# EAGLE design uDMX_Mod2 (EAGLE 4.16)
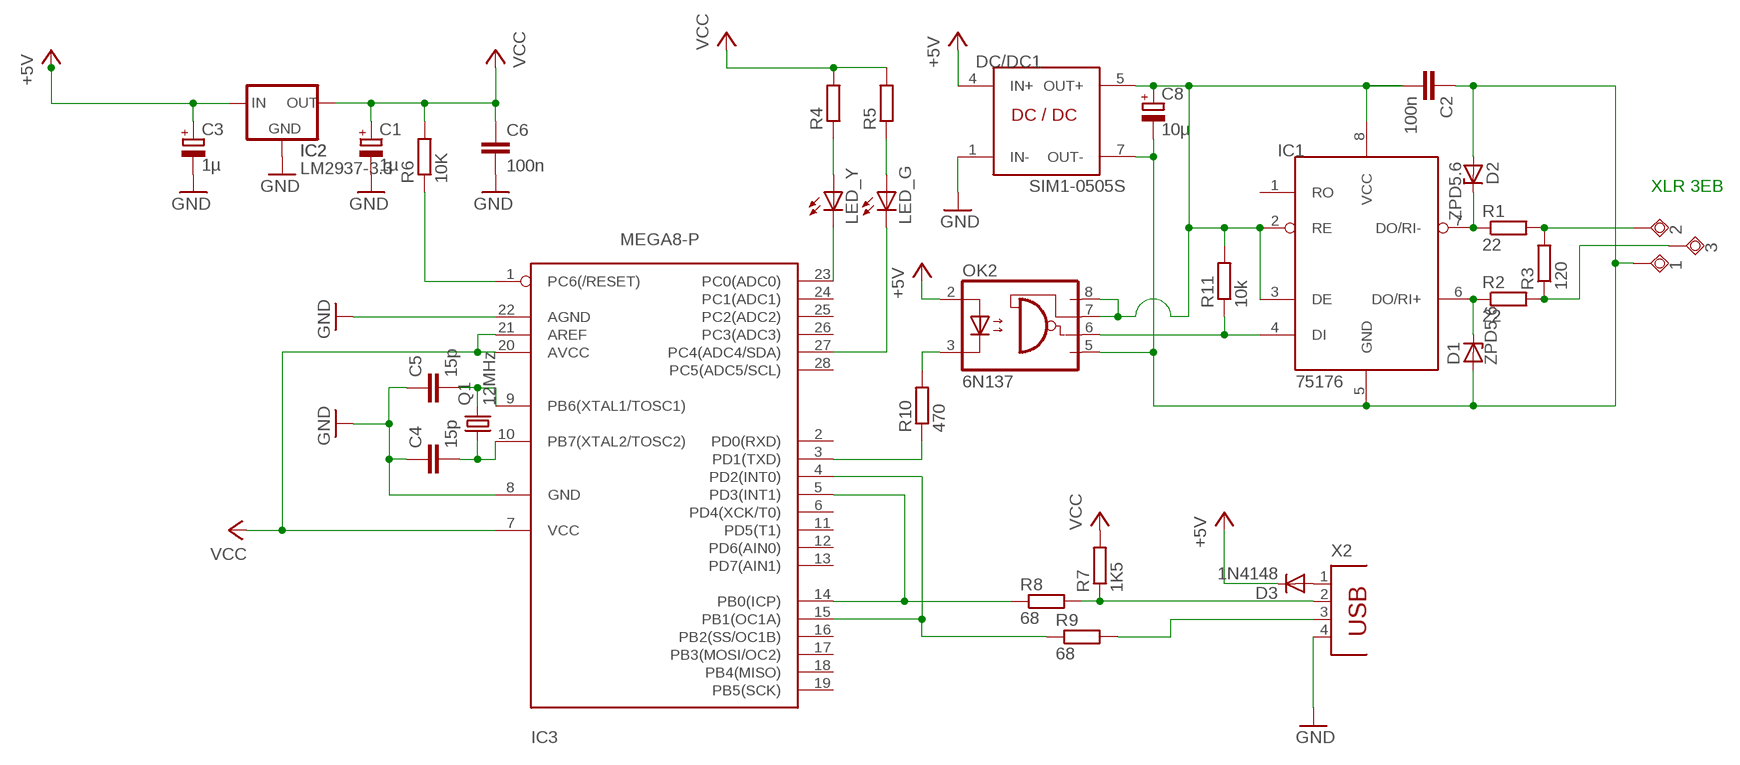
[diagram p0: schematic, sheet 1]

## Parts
1  PAD  [PAD]
2  PAD  [PAD]
3  PAD  [PAD]
C1  1µ  CPOL-EUE2.5-5  [E2,5-5]
C2  100n  C2.5/4  [C2.5-4]
C3  1µ  CPOL-EUE2.5-5  [E2,5-5]
C4  15p  C2.5/4  [C2.5-4]
C5  15p  C2.5/4  [C2.5-4]
C6  100n  C2.5/4  [C2.5-4]
C8  10µ  CPOL-EUE2.5-5  [E2,5-5]
D1  ZPD5.6  ZPD  [DO35Z10]
D2  ZPD5.6  ZPD  [DO35Z10]
D3  1N4148  [DO35-10]
DC/DC1  SIM1-0505S  [DIL08]
IC1  75176  [DIL08]
IC2  LM2937-3.3  LM2937  [TO220S]
IC3  MEGA8-P  [DIL28-3]
LED_G  LED3MM  [LED3MM]
LED_Y  LED3MM  [LED3MM]
OK2  6N137  [DIL08]
Q1  12MHz  CRYSTALHC18U-V  [HC18U-V]
R1  22  R-EU_0207/10  [0207/10]
R2  22  R-EU_0207/10  [0207/10]
R3  120  R-EU_0207/10  [0207/10]
R4  R-EU_0207/10  [0207/10]
R5  R-EU_0207/10  [0207/10]
R6  10K  R-EU_0207/10  [0207/10]
R7  1K5  R-EU_0207/10  [0207/10]
R8  68  R-EU_0207/10  [0207/10]
R9  68  R-EU_0207/10  [0207/10]
R10  470  R-EU_0207/10  [0207/10]
R11  10k  R-EU_0207/10  [0207/10]
X2  PN61729  [PN61729]

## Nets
+5V: C3.+ D3.C DC/DC1.4(IN+) IC2.1(IN) OK2.2(A)
D-: R7.1 R8.2 X2.2
DMX2: 2.P$1(TP) R1.2 R3.2
GND: C1.- C3.- C4.1 C5.1 C6.2 DC/DC1.1(IN-) IC2.2(GND) IC3.8(GND) IC3.22(AGND) X2.4
N$1: IC3.5(PD3(INT1)) IC3.14(PB0(ICP)) R8.1
N$2: OK2.3(C) R10.2
N$3: D2.C IC1.7(DO/RI-) R1.1
N$4: D1.C IC1.6(DO/RI+) R2.1
N$5: IC3.3(PD1(TXD)) R10.1
N$6: IC3.4(PD2(INT0)) IC3.15(PB1(OC1A)) R9.1
N$7: LED_Y.A R4.1
N$8: LED_G.A R5.1
N$9: IC3.23(PC0(ADC0)) LED_Y.K(C)
N$10: R9.2 X2.3
N$11: IC3.27(PC4(ADC4/SDA)) LED_G.K(C)
N$13: 3.P$1(TP) R2.2 R3.1
N$14: D3.A X2.1
N$16: C2.2 C8.+ DC/DC1.5(OUT+) IC1.2(RE) IC1.3(DE) IC1.8(VCC) OK2.7(VE) OK2.8(VCC) R11.2
N$17: 1.P$1(TP) C2.1 C8.- D1.A D2.A DC/DC1.7(OUT-) IC1.5(GND) OK2.5(GND)
N$20: IC1.4(DI) OK2.6(VO) R11.1
N$37: C4.2 IC3.10(PB7(XTAL2/TOSC2)) Q1.1
N$38: C5.2 IC3.9(PB6(XTAL1/TOSC1)) Q1.2
N$47: IC3.1(PC6(/RESET)) R6.1
VCC: C1.+ C6.1 IC2.3(OUT) IC3.7(VCC) IC3.20(AVCC) IC3.21(AREF) R4.2 R5.2 R6.2 R7.2
Unconnected: IC1.1(RO) IC3.2(PD0(RXD)) IC3.6(PD4(XCK/T0)) IC3.11(PD5(T1)) IC3.12(PD6(AIN0)) IC3.13(PD7(AIN1)) IC3.16(PB2(SS/OC1B)) IC3.17(PB3(MOSI/OC2)) IC3.18(PB4(MISO)) IC3.19(PB5(SCK)) IC3.24(PC1(ADC1)) IC3.25(PC2(ADC2)) IC3.26(PC3(ADC3)) IC3.28(PC5(ADC5/SCL))

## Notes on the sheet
- XLR 3EB

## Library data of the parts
1-3 = div:PAD
C1 C3 C8 = rcl:CPOL-EU: POLARIZED CAPACITOR, European symbol
C2 C4-C6 = capacitor-wima:C: CAPACITOR
D1 D2 = diode:ZPD: Z DIODE
D3 = diode:1N4148: DIODE
DC/DC1 = Lutz:SIM1-0505S
IC1 = Lutz:75176
IC2 = Lutz:LM2937: VOLTAGE REGULATOR
IC3 = atmel:MEGA8-P: MICROCONTROLLER 8 Kbytes FLASH 1 kbytes SRAM 512 bytes EEPROM USART 4-channel 10 bit ADC 2-channel 8 bit ADC Source: avr.lbr
LED_G LED_Y = led:LED: LED
OK2 = optocoupler:6N137: MOTOROLA OPTO COUPLER
Q1 = crystal:CRYSTAL: CRYSTAL
R1-R11 = rcl:R-EU_: RESISTOR, European symbol
X2 = con-berg:PN61729: BERG USB connector

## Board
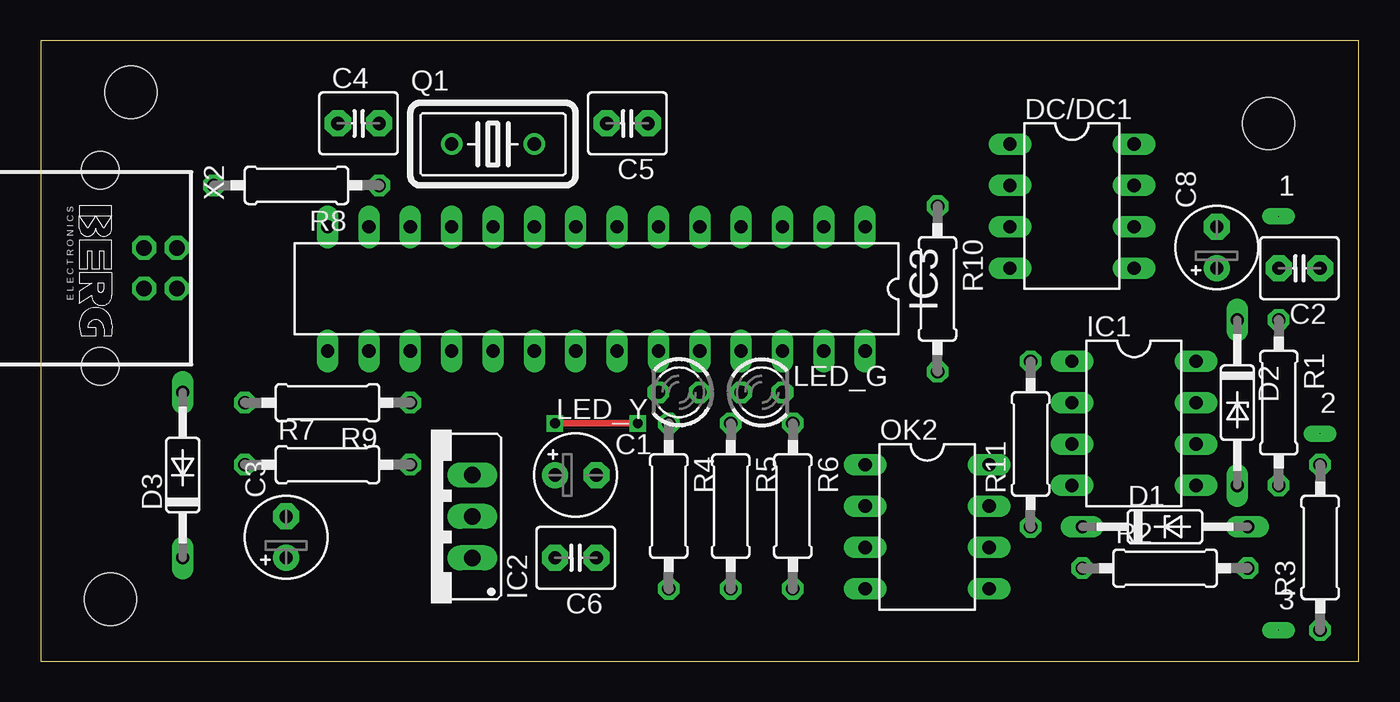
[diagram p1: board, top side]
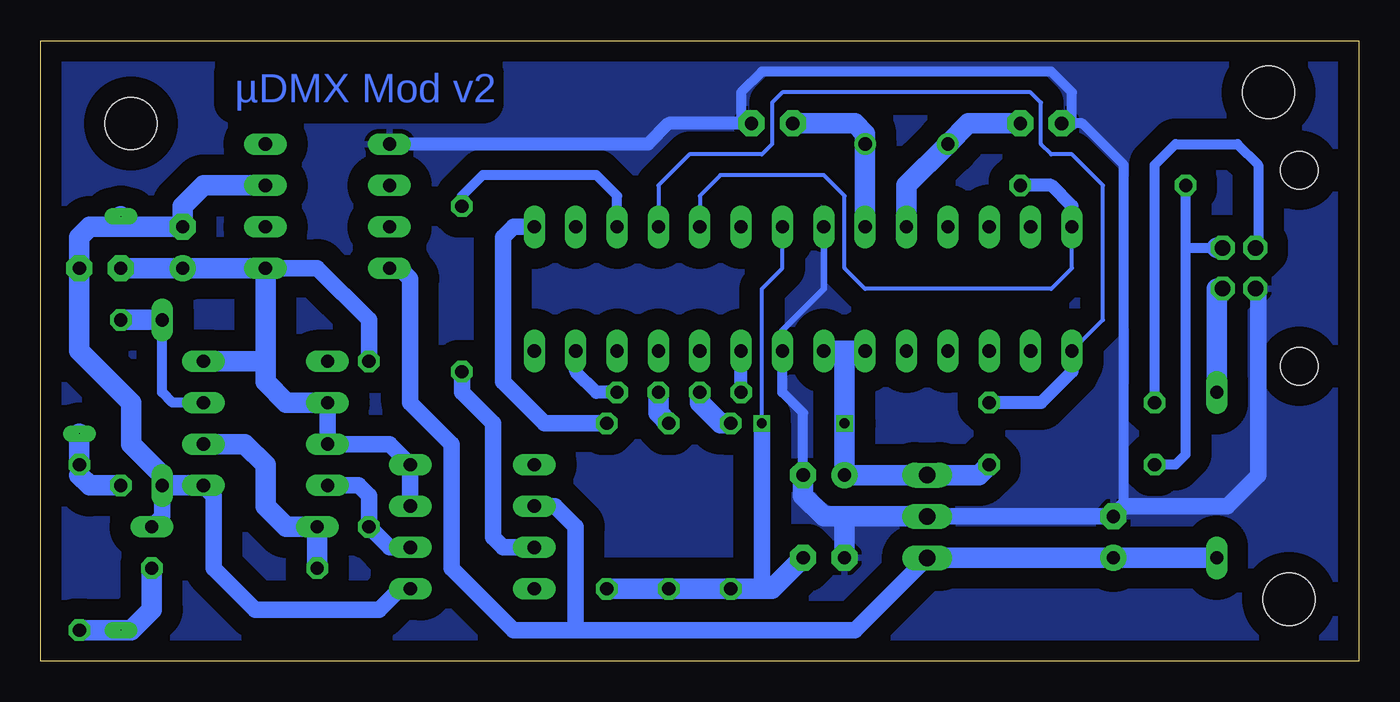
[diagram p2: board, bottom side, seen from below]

Size 80.95 x 38.09 mm. Coordinates in mm from the lower left corner, seen from the top.
Outline: 0,0 80.95,0 80.95,38.09 0,38.09 0,0
Copper layers (1*16): Top 0.035mm / dielectric 1.5mm / Bottom 0.035mm
Design rules "default": minimum track width 10mil, minimum drill 24mil, track to track 8mil, track to pad 8mil, pad to pad 8mil, via to via 8mil, smd to smd 8mil, copper to edge 40mil, drill to drill 8mil, minimum pad ring 10mil, minimum via ring 8mil, stop-mask expansion 4mil, vias tented up to drill 0mil, thermal gap 10mil
Holes 3.2 mm at 5.55,34.92 75.4,33.02 4.28,3.8

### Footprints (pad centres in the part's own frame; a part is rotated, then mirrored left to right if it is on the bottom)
PAD = drill 0.031 pad 1.016 long: P$1 0,0
E2,5-5 = drill 0.813 pad 1.6 round: + -1.27,0 | drill 0.813 pad 1.6 octagon: - 1.27,0
C2.5-4 = drill 0.813 pad 1.6 octagon: 1 -1.27,0; 2 1.27,0
DO35Z10 = drill 0.813 long: A 5.08,0; C -5.08,0
DO35-10 = drill 0.813 long: A 5.08,0; C -5.08,0
DIL08 = drill 0.813 long: 1 -3.81,-3.81; 2 -1.27,-3.81; 3 1.27,-3.81; 4 3.81,-3.81; 5 3.81,3.81; 6 1.27,3.81; 7 -1.27,3.81; 8 -3.81,3.81
TO220S = drill 1.016 long: 1 -2.54,-2.54; 2 0,-2.54; 3 2.54,-2.54
DIL28-3 = drill 0.813 long: 1 -16.51,-3.81; 2 -13.97,-3.81; 3 -11.43,-3.81; 4 -8.89,-3.81; 5 -6.35,-3.81; 6 -3.81,-3.81; 7 -1.27,-3.81; 8 1.27,-3.81; 9 3.81,-3.81; 10 6.35,-3.81; 11 8.89,-3.81; 12 11.43,-3.81; 13 13.97,-3.81; 14 16.51,-3.81; 15 16.51,3.81; 16 13.97,3.81; 17 11.43,3.81; 18 8.89,3.81; 19 6.35,3.81; 20 3.81,3.81; 21 1.27,3.81; 22 -1.27,3.81; 23 -3.81,3.81; 24 -6.35,3.81; 25 -8.89,3.81; 26 -11.43,3.81; 27 -13.97,3.81; 28 -16.51,3.81
LED3MM = drill 0.813 octagon: A -1.27,0; K 1.27,0
HC18U-V = drill 0.813 round: 1 -2.54,0; 2 2.54,0
0207/10 = drill 0.813 octagon: 1 -5.08,0; 2 5.08,0
PN61729 = drill 0.95 octagon: 1 1.25,4.71; 2 -1.25,4.71; 3 -1.25,2.71; 4 1.25,2.71 | hole 2.3: -6.02,0; 6.02,0

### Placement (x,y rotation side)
1  76.04,27.3 0 top
2  78.58,13.96 0 top
3  76.04,1.9 0 top
C1  32.85,11.43 0 top
C2  77.31,24.12 180 top
C3  15.08,7.61 90 top
C4  19.52,33.02 0 top
C5  36.03,33.02 180 top
C6  32.85,6.34 180 top
C8  72.23,25.39 90 top
D1  69.05,8.25 0 top
D2  73.5,15.87 270 top
D3  8.72,11.43 90 top
DC/DC1  63.33,27.94 270 top
IC1  67.15,14.6 270 top
IC2  23.96,8.88 90 top
IC3  34.12,22.85 180 top
LED_G  44.28,16.51 0 top
LED_Y  39.2,16.51 180 top
OK2  54.45,8.25 270 top
Q1  27.78,31.74 0 top
R1  76.04,15.87 270 top
R2  69.05,5.71 0 top
R3  78.58,6.98 90 top
R4  38.57,9.52 270 top
R5  42.38,9.52 270 top
R6  46.19,9.52 270 top
R7  17.62,12.06 0 top
R8  15.71,29.2 180 top
R9  17.62,15.87 180 top
R10  55.08,22.85 270 top
R11  60.79,13.33 90 top
X2  3.65,24.12 270 top

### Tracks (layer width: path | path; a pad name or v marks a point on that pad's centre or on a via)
+5V
  Bottom 1.016: IC2.1 30.95,1.9 48.09,1.9 | 48.09,1.9 51.9,1.9 55.71,5.71 55.71,13.33 58.25,15.87 58.25,23.49 58.89,24.12 DC/DC1.4 | OK2.2 49.36,9.52 48.09,8.25 48.09,1.9
  Bottom 1.27: D3.C C3.+ IC2.1
D-
  Bottom 0.61: R7.1 11.27,12.06 10.63,12.7 10.63,25.39 | 10.63,25.39 8.72,25.39 | 10.63,25.39 R8.2
  Bottom 1.27: 8.72,25.39 X2.2
DMX2
  Bottom 0.406: 78.58,11.43 R3.2
  Bottom 1.27: R1.2 77.94,10.79 78.58,11.43 | R3.2 2.P$1
GND
  Bottom 0.406: IC3.8 32.85,22.85 35.39,20.31 IC3.22
  Bottom 0.61: 37.93,33.02 37.93,34.92 36.66,36.19 18.89,36.19 17.62,34.92 17.62,33.02 16.98,33.02 14.44,30.48 14.44,9.52 | IC3.22 35.39,16.51 34.12,15.23 C1.-
  Bottom 0.813: DC/DC1.1 43.65,31.74 42.38,33.02 37.93,33.02 C5.1 | 17.62,33.02 C4.1
  Bottom 1.016: X2.4 6.19,22.88 6.19,11.43 8.09,9.52 14.44,9.52 C3.- IC2.2
  Bottom 1.27: IC2.2 31.59,8.88 | 31.59,8.88 32.85,8.88 34.12,10.16 C1.- | 31.59,8.88 C6.2
  pour Bottom (isolate 1.27): -0.8,38.73 81.75,38.73 81.75,-0.64 -0.8,-0.64
N$1
  Bottom 0.254: IC3.14 17.62,24.12 18.89,22.85 30.32,22.85 31.59,24.12 31.59,28.57 32.85,29.84 39.2,29.84 40.47,28.57 IC3.5
  Bottom 0.813: IC3.14 17.62,27.94 18.89,29.2 R8.1
N$2
  Bottom 1.016: OK2.3 52.54,6.98 53.17,7.61 53.17,14.6 55.08,16.51 R10.2
N$3
  Bottom 0.61: IC1.7 72.86,15.87 73.5,16.51 D2.C
  Bottom 1.27: D2.C R1.1
N$4
  Bottom 1.27: IC1.6 68.42,13.33 67.15,12.06 67.15,9.52 65.88,8.25 D1.C R2.1
N$5
  Bottom 0.61: R10.1 55.08,28.57 53.81,29.84 46.82,29.84 45.55,28.57 IC3.3
N$6
  Bottom 0.254: IC3.4 43.01,29.2 41.11,31.11 36.66,31.11 36.03,31.74 36.03,34.28 35.39,34.92 20.16,34.92 19.52,34.28 19.52,31.74 18.89,31.11 17.62,31.11 15.71,29.2 15.71,20.95 IC3.15
  Bottom 0.813: R9.1 19.52,15.87 17.62,17.77 IC3.15
N$7
  Bottom 1.27: R4.1 39.2,14.6 40.47,15.87 LED_Y.A
N$8
  Bottom 1.27: R5.1 43.01,15.23 LED_G.A
N$9
  Bottom 0.813: LED_Y.K IC3.23
N$10
  Bottom 0.406: 6.19,25.39 6.21,25.38 X2.3
  Bottom 0.61: R9.2 12.54,30.48 11.27,31.74 7.46,31.74 6.19,30.48 6.19,25.39
N$11
  Bottom 0.813: LED_G.K 46.82,16.51 48.09,17.77 IC3.27
N$13
  Bottom 1.27: R2.2 74.13,3.17 75.4,1.9 3.P$1 R3.1
N$14
  Bottom 1.27: D3.A 8.72,22.85 X2.1
N$16
  Bottom 1.016: IC1.2 IC1.3 59.52,13.33 OK2.8 OK2.7 | R11.2 60.79,20.95 63.97,24.12 DC/DC1.5
  Bottom 1.27: IC1.2 65.88,15.87 67.15,17.14 67.15,18.41 | 67.15,18.41 IC1.8 | 67.15,18.41 DC/DC1.5 C8.+ C2.2
N$17
  Bottom 1.016: IC1.5 70.32,10.16 70.32,5.71 67.78,3.17 60.16,3.17 58.89,4.44 OK2.5 | D1.A 73.5,8.88 D2.A
  Bottom 1.27: IC1.5 D2.A 73.5,11.43 75.4,13.33 75.4,15.87 78.58,19.05 C2.1 78.58,26.03 77.94,26.66 76.04,26.66 | DC/DC1.7 70.95,29.2 72.23,27.94 C8.- 76.04,26.66 | 76.04,26.66 1.P$1
N$20
  Bottom 1.016: OK2.6 59.52,6.98 R11.1 60.79,10.16 61.43,10.79 IC1.4
N$37
  Bottom 1.27: IC3.10 27.78,29.2 Q1.1 23.96,33.02 C4.2
N$38
  Bottom 1.27: IC3.9 Q1.2 30.32,32.38 30.95,33.02 C5.2
N$47
  Bottom 1.016: R6.1 50,14.6 52.54,17.14 52.54,26.03 51.9,26.66 IC3.1
VCC  (via drill 0.6)
  Top 0.406: v31.59,14.6 v36.66,14.6
  Bottom 0.254: IC3.7 35.39,24.12 36.66,22.85 v36.66,14.6
  Bottom 1.016: v36.66,14.6 36.66,4.44
  Bottom 1.27: R6.2 R5.2 R4.2 36.66,4.44 36.03,4.44 C6.1 | 31.59,19.05 IC3.21 | R7.2 23.33,11.43 IC2.3 C1.+ v31.59,14.6 31.59,19.05 | 31.59,19.05 IC3.20

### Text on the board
Bottom: µDMX Mod v2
